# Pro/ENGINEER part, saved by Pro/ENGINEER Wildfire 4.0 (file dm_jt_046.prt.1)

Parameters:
  METRIC = "NO"

Other parameters: PITCH, DRILL_POINT_ANGLE, DRILL_DEPTH, DRILL_DIAMETER, THREAD_DIAMETER, THREADS_PER_INCH, THREAD_DEPTH, THREAD_LENGTH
